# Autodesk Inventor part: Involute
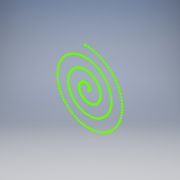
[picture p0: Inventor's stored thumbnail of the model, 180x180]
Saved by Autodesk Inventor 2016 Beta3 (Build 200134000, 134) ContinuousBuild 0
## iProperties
Created: 2008-02
Part Number: Involute
Document SubType Name: Modeling
Designer: Autodesk, Inc.
Density: 1 g/cm^3
Material: Generic
Appearance: Default
Author: Autodesk, Inc.
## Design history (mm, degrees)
sketch "Sketch1"
  geometry: 300 further points
  constraints: 300 other
